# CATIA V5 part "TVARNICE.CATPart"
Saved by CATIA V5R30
Part number: TVARNICE
Bounding box of the stored display mesh (mm): x -70 to 70, y -69.99 to 69.99, z -64.729 to 1.271
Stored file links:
  C:\Users\ondra\Desktop\PŘÍLOHA P III\CATIA\TVARNICE.CATPart
  C:\Users\ondra\Desktop\FORMA_BAKALARKA\Part1.CATPart
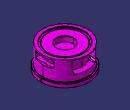
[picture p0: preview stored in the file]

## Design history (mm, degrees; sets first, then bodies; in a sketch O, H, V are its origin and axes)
Body1 (main body)
  Body2 "TVARNICE"
    Solid1: linked copy from another document
  Assemble1: tool Body2
  Plane1: type Offset, RefPlane yz-plane, Offset 70
  Sketch1 on Plane1, origin (70, 0, 0), H (0, 1, 0), V (0, 0, 1)
    construction circle A1 centre (0, -60.5285) radius 2.5
    point P1 (0, -60.5285)
    point P2 (0, -60.5285)
    reference projected line E1 (-70, -64.7285) -> (70, -64.7285) from edge [face of Solid1 | face of Solid1]
    radius A1 = 2.5
    distance P2 E1 = 4.2
    coincidence: P1 V, P2 P1
  Sketch2 on Plane1, origin (70, 0, -60.5285), H (0, 1, 0), V (0, 0, 1)
    point P1 (0, 0)
    reference projected point E1 (0, 0) from Sketch1.P2
    coincidence: E1 P1
  Hole1: placed by Sketch2, at (70, 0, -60.5285) direction (-1, 0, 0), diameter 5, depth 7, V-bottom angle 120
